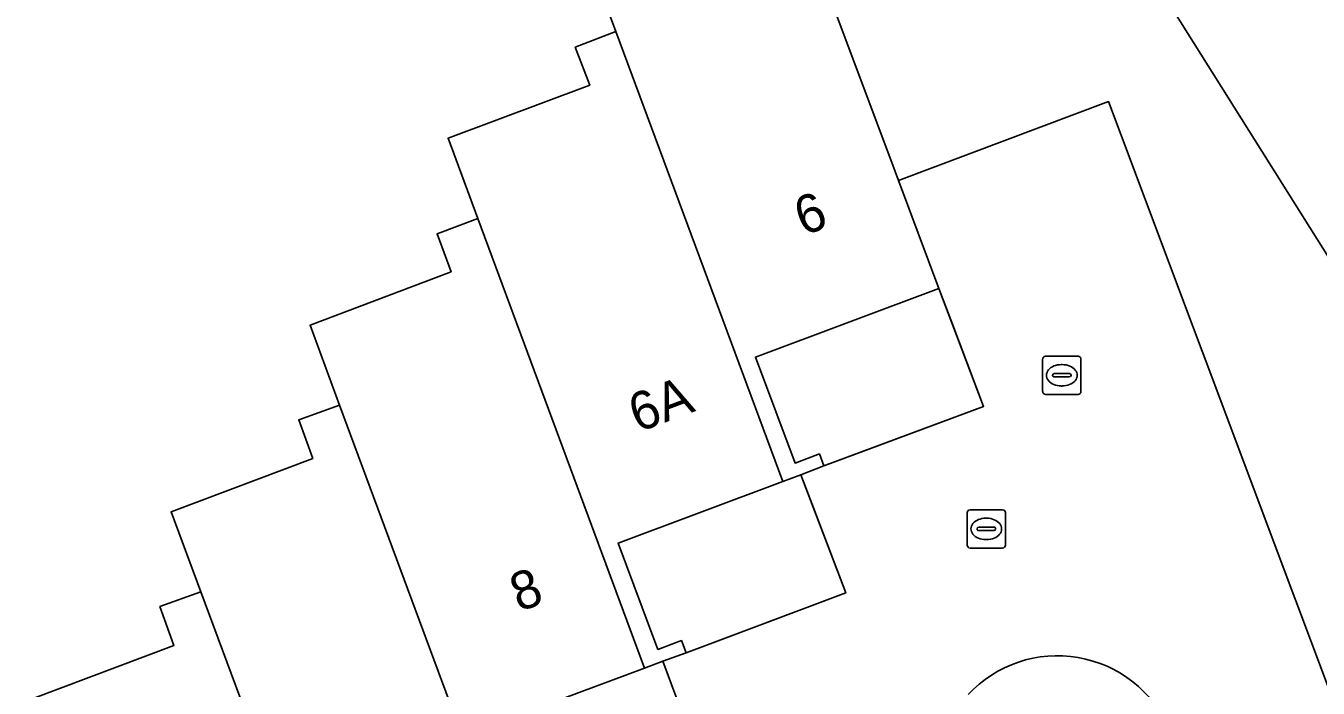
# Model space of a CAD drawing. Extents: x 160663 to 161506, y 382245 to 383291.
# Drawn here: x 160690.09 to 160723.87, y 383158.13 to 383175.45 of the extents above; entities that cross this region are included whole.
import ezdxf

# ---------------------------------------------------------------- set-up
doc = ezdxf.new("R2010")
doc.units = 0
for name, color, linetype in [('IMGEO_Erf', 7, 'Continuous'), ('IMGEO_Groenvoorziening', 7, 'Continuous'), ('IMGEO_Pand', 7, 'Continuous'), ('IMGEO_Pand_nummerreeks', 7, 'Continuous'), ('IMGEO_Pand_overbouw', 7, 'Continuous'), ('IMGEO_Rijbaan_lokaal_open', 7, 'Continuous'), ('IMGEO_Rioolput', 7, 'Continuous'), ('IMGEO_Voetpad_open', 7, 'Continuous')]:
    doc.layers.add(name, color=color, linetype=linetype)

msp = doc.modelspace()

# ---------------------------------------------------------------- linework, layer by layer
at = {"layer": 'IMGEO_Erf'}
for points in [[(160761.204, 383181.097), (160749.748, 383173.844), (160750.432, 383172.762), (160744.104, 383168.763), (160740.194, 383175.013), (160732.213, 383169.997), (160731.898, 383170.498), (160730.725, 383169.759), (160735.037, 383163.056), (160734.385, 383162.64), (160734.158, 383161.783), (160732.874, 383160.954), (160732.004, 383161.117), (160731.185, 383160.597), (160730.527, 383161.622), (160728.942, 383160.603), (160726.993, 383163.638), (160726.559, 383163.68), (160726.078, 383164.425), (160726.216, 383164.838), (160724.635, 383167.324), (160725.222, 383167.694), (160724.191, 383169.333), (160716.168, 383182.089)], [(160709.56, 383180.338), (160712.727, 383171.875), (160712.903, 383171.405), (160718.393, 383173.471), (160725.736, 383153.883), (160725.98, 383153.338), (160726.116, 383153.372), (160726.52, 383153.673), (160729.655, 383155.677), (160730.195, 383156.015), (160730.374, 383156.128), (160757.849, 383173.421), (160766.092, 383178.668)], [(160686.655, 383152.982), (160690.339, 383154.37), (160689.98, 383155.388), (160691.046, 383155.764), (160690.256, 383157.855), (160693.957, 383159.246), (160693.595, 383160.263), (160694.67, 383160.647), (160693.89, 383162.739), (160697.593, 383164.138), (160697.226, 383165.143), (160698.292, 383165.532), (160697.521, 383167.622), (160701.207, 383169.02), (160700.84, 383170.015), (160701.907, 383170.408), (160701.128, 383172.509), (160704.833, 383173.901), (160704.452, 383174.89), (160705.515, 383175.3), (160704.744, 383177.37)]]:
    msp.add_lwpolyline(points, dxfattribs=at)
at = {"layer": 'IMGEO_Groenvoorziening'}
msp.add_arc((160717.058, 383155.789), 3.19, 23.4227, 137.0636, dxfattribs=at)
at = {"layer": 'IMGEO_Pand'}
msp.add_lwpolyline([(160716.168, 383182.089), (160724.191, 383169.333), (160725.222, 383167.694), (160730.082, 383170.759), (160730.725, 383169.759), (160731.898, 383170.498), (160732.213, 383169.997), (160740.194, 383175.013), (160744.104, 383168.763), (160750.432, 383172.762), (160749.748, 383173.844), (160761.204, 383181.097)], dxfattribs=at)
for points in [[(160709.56, 383180.338), (160708.071, 383179.767), (160708.449, 383178.777), (160704.744, 383177.37), (160705.515, 383175.3), (160709.88, 383163.538), (160710.348, 383163.713), (160710.948, 383163.942), (160710.838, 383164.256), (160710.202, 383164.017), (160709.164, 383166.789), (160713.959, 383168.584), (160712.903, 383171.405), (160712.727, 383171.875)], [(160705.515, 383175.3), (160704.452, 383174.89), (160704.833, 383173.901), (160701.128, 383172.509), (160701.907, 383170.408), (160706.268, 383158.657), (160706.744, 383158.835), (160707.355, 383159.055), (160707.23, 383159.374), (160706.616, 383159.143), (160705.574, 383161.925), (160709.88, 383163.538)], [(160701.907, 383170.408), (160700.84, 383170.015), (160701.207, 383169.02), (160697.521, 383167.622), (160698.292, 383165.532), (160702.652, 383153.785), (160703.135, 383153.965), (160703.736, 383154.199), (160703.615, 383154.513), (160702.996, 383154.267), (160701.957, 383157.049), (160706.268, 383158.657)], [(160698.292, 383165.532), (160697.226, 383165.143), (160697.593, 383164.138), (160693.89, 383162.739), (160694.67, 383160.647), (160699.033, 383148.89), (160699.506, 383149.066), (160700.107, 383149.289), (160699.992, 383149.608), (160699.39, 383149.411), (160698.357, 383152.185), (160702.652, 383153.785)], [(160694.67, 383160.647), (160693.595, 383160.263), (160693.957, 383159.246), (160690.256, 383157.855), (160691.046, 383155.764), (160695.406, 383144.016), (160695.877, 383144.191), (160696.477, 383144.418), (160696.37, 383144.736), (160695.744, 383144.5), (160694.709, 383147.284), (160699.033, 383148.89)]]:
    msp.add_lwpolyline(points, close=True, dxfattribs=at)
at = {"layer": 'IMGEO_Pand_overbouw'}
for points in [[(160713.959, 383168.584), (160709.164, 383166.789), (160710.202, 383164.017), (160710.838, 383164.256), (160710.948, 383163.942), (160715.129, 383165.5)], [(160710.348, 383163.713), (160709.88, 383163.538), (160705.574, 383161.925), (160706.616, 383159.143), (160707.23, 383159.374), (160707.355, 383159.055), (160711.525, 383160.624)], [(160706.744, 383158.835), (160706.268, 383158.657), (160701.957, 383157.049), (160702.996, 383154.267), (160703.615, 383154.513), (160703.736, 383154.199), (160707.897, 383155.738)]]:
    msp.add_lwpolyline(points, close=True, dxfattribs=at)
at = {"layer": 'IMGEO_Rijbaan_lokaal_open'}
msp.add_lwpolyline([(160725.736, 383153.883), (160718.393, 383173.471), (160712.903, 383171.405), (160713.959, 383168.584), (160714.272, 383167.758), (160715.129, 383165.5), (160711.685, 383164.217), (160710.948, 383163.942), (160710.348, 383163.713), (160710.68, 383162.842), (160711.525, 383160.624), (160708.124, 383159.344), (160707.355, 383159.055), (160706.744, 383158.835), (160707.084, 383157.921)], dxfattribs=at)
msp.add_arc((160717.058, 383155.789), 3.19, 23.4227, 137.0636, dxfattribs=at)
at = {"layer": 'IMGEO_Rioolput'}
for p, q in [((160716.673, 383165.886), (160716.673, 383166.738)), ((160716.748, 383166.812), (160717.6, 383166.812)), ((160717.161, 383166.592), (160717.186, 383166.592)), ((160717.674, 383166.738), (160717.674, 383165.886)), ((160716.932, 383166.306), (160716.932, 383166.318)), ((160717.37, 383166.269), (160716.972, 383166.269)), ((160716.975, 383166.355), (160717.373, 383166.355)), ((160717.416, 383166.318), (160717.416, 383166.306)), ((160717.184, 383166.032), (160717.159, 383166.032)), ((160717.6, 383165.812), (160716.748, 383165.812)), ((160714.699, 383161.869), (160714.699, 383162.721)), ((160714.774, 383162.795), (160715.626, 383162.795)), ((160715.187, 383162.575), (160715.212, 383162.575)), ((160715.7, 383162.721), (160715.7, 383161.869)), ((160714.958, 383162.289), (160714.958, 383162.301)), ((160715.396, 383162.252), (160714.998, 383162.252)), ((160715.001, 383162.338), (160715.399, 383162.338)), ((160715.442, 383162.301), (160715.442, 383162.289)), ((160715.21, 383162.015), (160715.185, 383162.015)), ((160715.626, 383161.795), (160714.774, 383161.795))]:
    msp.add_line(p, q, dxfattribs=at)
for points in [[(160716.673, 383165.886), (160716.673, 383166.738)], [(160716.748, 383166.812), (160717.6, 383166.812)], [(160717.674, 383166.738), (160717.674, 383165.886)], [(160717.6, 383165.812), (160716.748, 383165.812)], [(160714.699, 383161.869), (160714.699, 383162.721)], [(160714.774, 383162.795), (160715.626, 383162.795)], [(160715.7, 383162.721), (160715.7, 383161.869)], [(160715.626, 383161.795), (160714.774, 383161.795)]]:
    msp.add_lwpolyline(points, dxfattribs=at)
for centre, radius, start, end in [((160716.75, 383166.736), 0.0765, 91.552, 178.448), ((160716.75, 383166.736), 0.0765, 91.552, 178.448), ((160717.598, 383166.736), 0.0765, 1.552, 88.448), ((160717.598, 383166.736), 0.0765, 1.552, 88.448), ((160716.972, 383166.315), 0.0403, 85.8775, 175.7526), ((160716.969, 383166.305), 0.0366, 178.938, 274.7102), ((160717.373, 383166.312), 0.043, 264.8664, 352.4533), ((160717.377, 383166.317), 0.0386, 1.7309, 96.639), ((160716.75, 383165.888), 0.0765, 181.552, 268.448), ((160716.75, 383165.888), 0.0765, 181.552, 268.448), ((160717.598, 383165.888), 0.0765, 271.552, 358.448), ((160717.598, 383165.888), 0.0765, 271.552, 358.448), ((160714.776, 383162.719), 0.0765, 91.552, 178.448), ((160714.776, 383162.719), 0.0765, 91.552, 178.448), ((160715.624, 383162.719), 0.0765, 1.552, 88.448), ((160715.624, 383162.719), 0.0765, 1.552, 88.448), ((160714.998, 383162.298), 0.0403, 85.8775, 175.7526), ((160714.995, 383162.288), 0.0366, 178.938, 274.7102), ((160715.399, 383162.295), 0.043, 264.8664, 352.4533), ((160715.403, 383162.3), 0.0386, 1.7309, 96.639), ((160714.776, 383161.871), 0.0765, 181.552, 268.448), ((160714.776, 383161.871), 0.0765, 181.552, 268.448), ((160715.624, 383161.871), 0.0765, 271.552, 358.448), ((160715.624, 383161.871), 0.0765, 271.552, 358.448)]:
    msp.add_arc(centre, radius, start, end, dxfattribs=at)
for centre, major_axis, ratio, start_param, end_param in [((160717.16, 383166.312), (-0.387, 0.002), 0.722429, 4.712389, 7.853982), ((160717.185, 383166.312), (-0.39, 0.002), 0.717154, 1.570796, 4.712389), ((160715.186, 383162.295), (-0.387, 0.002), 0.722429, 4.712389, 7.853982), ((160715.211, 383162.295), (-0.39, 0.002), 0.717154, 1.570796, 4.712389)]:
    msp.add_ellipse(centre, major_axis=major_axis, ratio=ratio, start_param=start_param, end_param=end_param, dxfattribs=at)
at = {"layer": 'IMGEO_Voetpad_open'}
for points in [[(160713.959, 383168.584), (160709.164, 383166.789), (160710.202, 383164.017), (160710.838, 383164.256), (160710.948, 383163.942), (160711.685, 383164.217), (160715.129, 383165.5), (160714.272, 383167.758)], [(160708.124, 383159.344), (160711.525, 383160.624), (160710.68, 383162.842), (160710.348, 383163.713), (160709.88, 383163.538), (160705.574, 383161.925), (160706.616, 383159.143), (160707.23, 383159.374), (160707.355, 383159.055)], [(160704.597, 383154.517), (160707.897, 383155.738), (160707.084, 383157.921), (160706.744, 383158.835), (160706.268, 383158.657), (160701.957, 383157.049), (160702.996, 383154.267), (160703.615, 383154.513), (160703.736, 383154.199)]]:
    msp.add_lwpolyline(points, close=True, dxfattribs=at)

# ---------------------------------------------------------------- texts
at = {"layer": 'IMGEO_Pand_nummerreeks'}
for s, rotation, p in [('6', 20.5233, (160710.42, 383169.95)), ('6A', 20.542, (160706.091, 383164.809)), ('8', 20.3161, (160702.985, 383160.116))]:
    msp.add_text(s, height=1, rotation=rotation, dxfattribs=at).set_placement(p)

doc.saveas('drawing.dxf')
